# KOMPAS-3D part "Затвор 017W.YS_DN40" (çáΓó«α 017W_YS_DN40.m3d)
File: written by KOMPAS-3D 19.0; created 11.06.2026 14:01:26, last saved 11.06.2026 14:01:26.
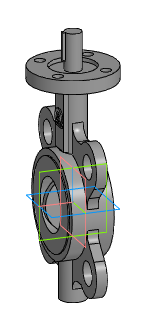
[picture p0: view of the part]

Document properties: Автор: Евгений; Полное имя файла: Z:\3.Личные\kachalov\001_3d для проектировщиков\x.x Тип 017W.Y(S) Затвор дисковый поворотный межфланцевый\_stp_Затвор 017W.YS_DN32-DN1200\Затвор 017W_YS_DN40.m3d

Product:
- Part/product: Затвор 017W.YS_DN40

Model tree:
1. Операция без истории:1  (labels: Затвор 017W.YS_DN40)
